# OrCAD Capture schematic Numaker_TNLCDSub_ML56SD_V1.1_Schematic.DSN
size A; title: LCD Connector; rev: v1.1; note: NuMaker-TNLCDSub_ML56SD V1.1
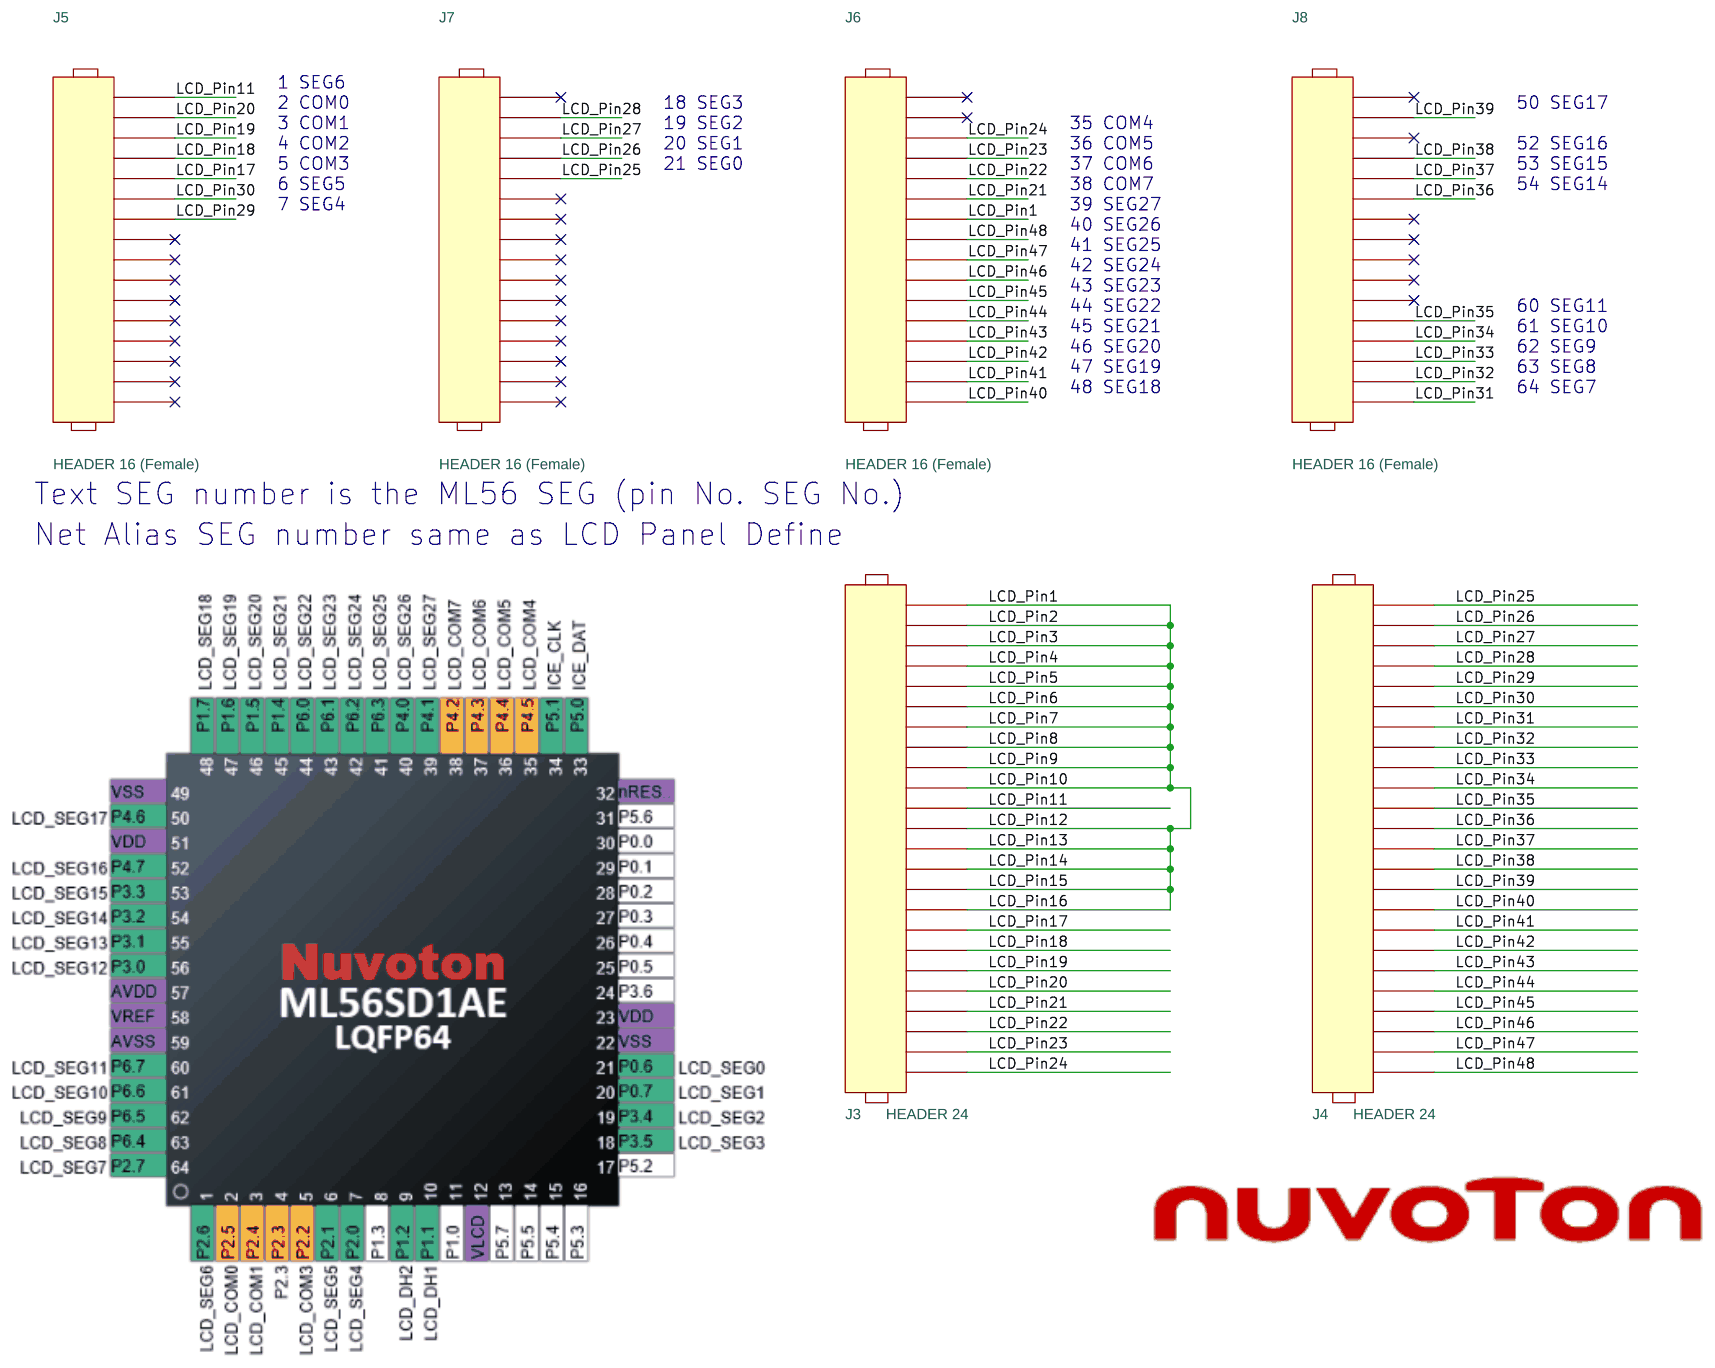
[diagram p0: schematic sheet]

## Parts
J3  HEADER 24  [HEADER24]
J4  HEADER 24  [HEADER24]
J5  HEADER 16 (Female)  [HEADER16]
J6  HEADER 16 (Female)  [HEADER16]
J7  HEADER 16 (Female)  [HEADER16]
J8  HEADER 16 (Female)  [HEADER16]

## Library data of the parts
J3 J4 = HEADER_24
J5-J8 = HEADER_16

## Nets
LCD_Pin1: J3.1 J3.2 J3.3 J3.4 J3.5 J3.6 J3.7 J3.8 J3.9 J3.10 J3.12 J3.13 J3.14 J3.15 J3.16 J6.7
LCD_Pin11: J3.11 J5.1
LCD_Pin17: J3.17 J5.5
LCD_Pin18: J3.18 J5.4
LCD_Pin19: J3.19 J5.3
LCD_Pin20: J3.20 J5.2
LCD_Pin21: J3.21 J6.6
LCD_Pin22: J3.22 J6.5
LCD_Pin23: J3.23 J6.4
LCD_Pin24: J3.24 J6.3
LCD_Pin25: J4.1 J7.5
LCD_Pin26: J4.2 J7.4
LCD_Pin27: J4.3 J7.3
LCD_Pin28: J4.4 J7.2
LCD_Pin29: J4.5 J5.7
LCD_Pin30: J4.6 J5.6
LCD_Pin31: J4.7 J8.16
LCD_Pin32: J4.8 J8.15
LCD_Pin33: J4.9 J8.14
LCD_Pin34: J4.10 J8.13
LCD_Pin35: J4.11 J8.12
LCD_Pin36: J4.12 J8.6
LCD_Pin37: J4.13 J8.5
LCD_Pin38: J4.14 J8.4
LCD_Pin39: J4.15 J8.2
LCD_Pin40: J4.16 J6.16
LCD_Pin41: J4.17 J6.15
LCD_Pin42: J4.18 J6.14
LCD_Pin43: J4.19 J6.13
LCD_Pin44: J4.20 J6.12
LCD_Pin45: J4.21 J6.11
LCD_Pin46: J4.22 J6.10
LCD_Pin47: J4.23 J6.9
LCD_Pin48: J4.24 J6.8

Not connected (* = marked no-connect by the designer): J5 8* 9* 10* 11* 12* 13* 14* 15* 16*; J6 1* 2*; J7 1* 6* 7* 8* 9* 10* 11* 12* 13* 14* 15* 16*; J8 1* 3* 7* 8* 9* 10* 11*

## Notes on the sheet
- 1 SEG6
- 2 COM0
- 18 SEG3
- 50 SEG17
- 3 COM1
- 19 SEG2
- 35 COM4
- 4 COM2
- 20 SEG1
- 36 COM5
- 52 SEG16
- 5 COM3
- 21 SEG0
- 37 COM6
- 53 SEG15
- 6 SEG5
- 38 COM7
- 54 SEG14
- 7 SEG4
- 39 SEG27
- 40 SEG26
- 41 SEG25
- 42 SEG24
- 43 SEG23
- 44 SEG22
- 60 SEG11
- 45 SEG21
- 46 SEG20
- 61 SEG10
- 62 SEG9
- 47 SEG19
- 63 SEG8
- 48 SEG18
- 64 SEG7
- Text SEG number is the ML56 SEG (pin No. SEG No.)
- Net Alias SEG number same as LCD Panel Define
